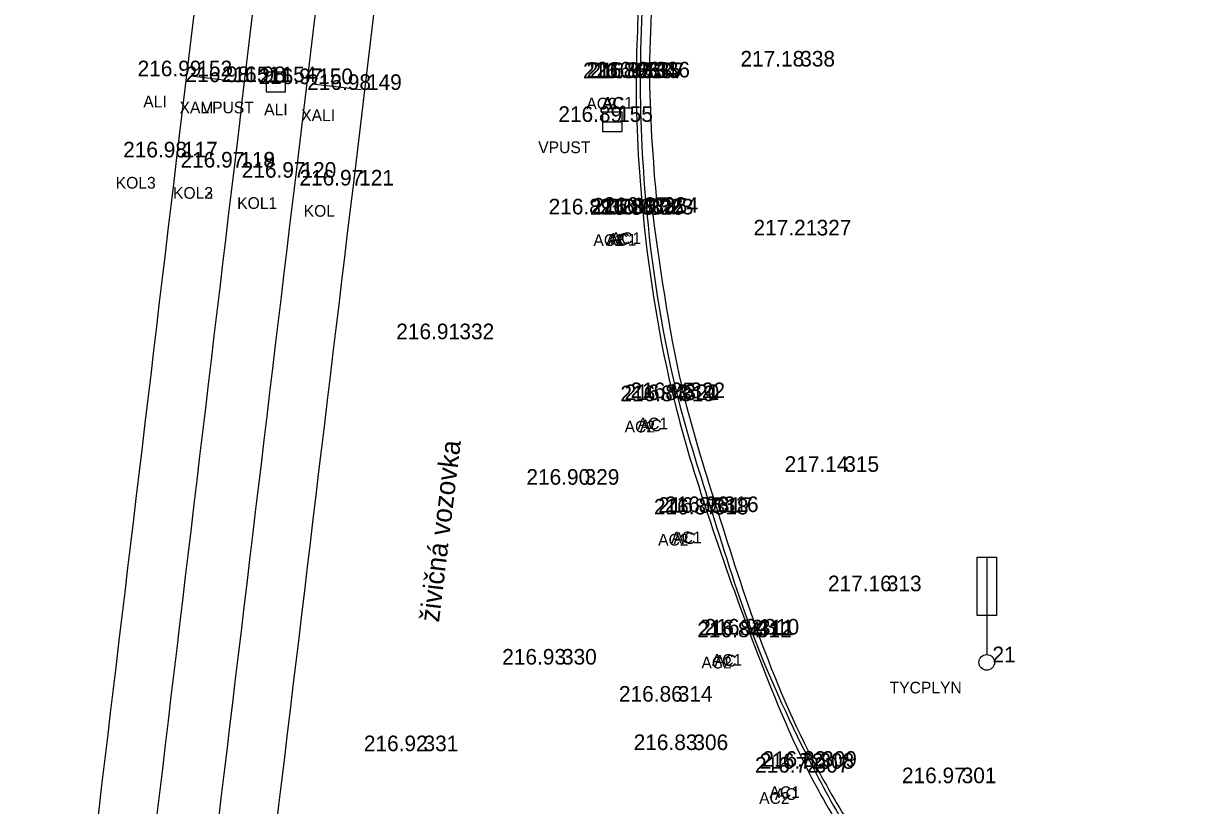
# Model space of a CAD drawing. Extents: x -471047 to -470889, y -1102859 to -1102000.
# Drawn here: x -471001.01 to -470970.75, y -1102729.15 to -1102709.11 of the extents above; entities that cross this region are included whole.
import ezdxf

# ---------------------------------------------------------------- set-up
doc = ezdxf.new("R2010")
doc.units = 0
for name, color, linetype in [('Vrstva 1', 7, 'Continuous'), ('Vrstva 11', 7, 'Continuous'), ('Vrstva 22', 7, 'Continuous'), ('Vrstva 25', 7, 'Continuous'), ('Vrstva 29', 7, 'Continuous'), ('Vrstva 34', 7, 'Continuous'), ('Vrstva 35', 7, 'Continuous'), ('Vrstva 36', 7, 'Continuous'), ('Vrstva 38', 7, 'Continuous'), ('Vrstva 5', 7, 'Continuous'), ('Vrstva 7', 7, 'Continuous'), ('Vrstva 8', 7, 'Continuous')]:
    doc.layers.add(name, color=color, linetype=linetype)

msp = doc.modelspace()

# ---------------------------------------------------------------- linework, layer by layer
at = {"layer": 'Vrstva 1'}
for points in [[(-471040.344, -1102858.385), (-471031.676, -1102846.187), (-471026.357, -1102838.629), (-471023.212, -1102833.975), (-471019.21, -1102827.465), (-471016.861, -1102823.272), (-471013.099, -1102815.912), (-471010.824, -1102810.955), (-471007.329, -1102802.292), (-471005.34, -1102796.515), (-471002.842, -1102787.838), (-471001.3, -1102780.997), (-471000.19, -1102774.713), (-470999.247, -1102768.204), (-470998.794, -1102764.784), (-470997.199, -1102751.812), (-470994.899, -1102732.807), (-470992.551, -1102713.262), (-470990.326, -1102694.887), (-470988.122, -1102676.57), (-470985.812, -1102657.305), (-470983.537, -1102638.407), (-470981.386, -1102620.622), (-470979.843, -1102608.014), (-470976.377, -1102579.253), (-470972.945, -1102550.69), (-470970.475, -1102530.206), (-470967.905, -1102508.801), (-470965.053, -1102485.131), (-470962.734, -1102465.9), (-470960.173, -1102444.812), (-470957.795, -1102425.103), (-470954.965, -1102401.839), (-470953.834, -1102392.574), (-470952.33, -1102379.985), (-470950.744, -1102366.853), (-470948.978, -1102352.106), (-470947.037, -1102335.844), (-470944.949, -1102318.462), (-470944.013, -1102310.745), (-470942.39, -1102297.267), (-470939.519, -1102273.45), (-470937.593, -1102257.43), (-470936.064, -1102244.81), (-470934.114, -1102228.634), (-470931.621, -1102207.856), (-470929.536, -1102190.857), (-470926.572, -1102166.31), (-470924.91, -1102152.663), (-470923.413, -1102140.333), (-470921.923, -1102127.669), (-470921.155, -1102120.084), (-470920.446, -1102109.574), (-470919.912, -1102099.137), (-470919.63, -1102088.981), (-470919.523, -1102081.193), (-470919.563, -1102070.395), (-470919.714, -1102064.236), (-470920.134, -1102054.704), (-470920.462, -1102047.615), (-470920.599, -1102044.52), (-470920.743, -1102041.873), (-470921.125, -1102034.455), (-470921.774, -1102030.337), (-470922.418, -1102027.787), (-470923.734, -1102023.93), (-470924.872, -1102021.434), (-470926.752, -1102018.182), (-470927.953, -1102016.45), (-470929.616, -1102014.424), (-470932.252, -1102011.756), (-470935.111, -1102009.425), (-470938.391, -1102007.371), (-470942.651, -1102005.401)], [(-471041.328, -1102857.18), (-471032.144, -1102844.242), (-471027.583, -1102837.763), (-471024.388, -1102833.028), (-471020.451, -1102826.6), (-471018.089, -1102822.378), (-471014.542, -1102815.445), (-471012.233, -1102810.418), (-471009.247, -1102803.108), (-471006.795, -1102796.098), (-471004.315, -1102787.532), (-471002.782, -1102780.723), (-471001.674, -1102774.458), (-471000.75, -1102768.095), (-471000.28, -1102764.601), (-470998.692, -1102751.741), (-470996.378, -1102732.635), (-470994.028, -1102713.058), (-470991.808, -1102694.749), (-470989.616, -1102676.447), (-470987.284, -1102657.013), (-470985.031, -1102638.272), (-470982.87, -1102620.431), (-470981.334, -1102607.933), (-470977.881, -1102579.263), (-470974.429, -1102550.492), (-470971.964, -1102530.054), (-470969.391, -1102508.607), (-470966.54, -1102484.984), (-470964.231, -1102465.853), (-470961.679, -1102444.752), (-470959.304, -1102425.078), (-470956.455, -1102401.634), (-470955.339, -1102392.489), (-470953.812, -1102379.71), (-470952.249, -1102366.808), (-470950.479, -1102352.023), (-470948.536, -1102335.868), (-470946.426, -1102318.233), (-470945.493, -1102310.531), (-470943.864, -1102297.013), (-470940.984, -1102273.071), (-470939.078, -1102257.195), (-470937.559, -1102244.684), (-470935.592, -1102228.353), (-470933.101, -1102207.653), (-470931.011, -1102190.57), (-470928.046, -1102166.021), (-470926.409, -1102152.578), (-470924.898, -1102140.121), (-470923.427, -1102127.544), (-470922.647, -1102119.826), (-470921.919, -1102109.229), (-470921.42, -1102099.134), (-470921.127, -1102089.016), (-470921.023, -1102081.453), (-470921.061, -1102070.468), (-470921.209, -1102064.314), (-470921.666, -1102053.966), (-470922.156, -1102043.345), (-470922.299, -1102039.934), (-470922.637, -1102034.36), (-470923.091, -1102031.241), (-470923.847, -1102028.247), (-470925.083, -1102024.594), (-470926.222, -1102022.086), (-470928.04, -1102018.943), (-470929.138, -1102017.357), (-470930.929, -1102015.175), (-470933.062, -1102013.049), (-470936.379, -1102010.368), (-470939.169, -1102008.662), (-470942.899, -1102006.906), (-470945.661, -1102005.908)], [(-471043.557, -1102855.955), (-471035.129, -1102844.026), (-471029.872, -1102836.499), (-471026.577, -1102831.578), (-471022.675, -1102825.415), (-471020.123, -1102821.053), (-471016.667, -1102814.59), (-471014.208, -1102809.45), (-471011.177, -1102802.451), (-471008.55, -1102795.333), (-471006.082, -1102787.209), (-471004.464, -1102780.376), (-471003.265, -1102774.167), (-471002.327, -1102767.948), (-471001.636, -1102762.527), (-471000.297, -1102751.605), (-470997.959, -1102732.524), (-470995.602, -1102712.802), (-470993.412, -1102694.623), (-470991.21, -1102676.17), (-470988.891, -1102656.857), (-470986.625, -1102638.083), (-470984.455, -1102620.195), (-470982.936, -1102607.733), (-470979.497, -1102579.223), (-470976.023, -1102550.279), (-470973.554, -1102529.822), (-470970.991, -1102508.497), (-470968.146, -1102484.787), (-470965.835, -1102465.72), (-470963.284, -1102444.529), (-470960.91, -1102424.942), (-470958.043, -1102401.343), (-470956.946, -1102392.356), (-470955.396, -1102379.408), (-470953.851, -1102366.636), (-470952.049, -1102351.733), (-470950.124, -1102335.611), (-470948.034, -1102318.083), (-470947.094, -1102310.328), (-470945.421, -1102296.51), (-470942.58, -1102272.848), (-470940.675, -1102256.948), (-470939.176, -1102244.526), (-470937.187, -1102228.174), (-470934.708, -1102207.467), (-470932.621, -1102190.433), (-470929.634, -1102165.778), (-470928.004, -1102152.415), (-470926.45, -1102139.595), (-470925.003, -1102127.418), (-470924.249, -1102119.695), (-470923.515, -1102109.093), (-470923.018, -1102099.069), (-470922.711, -1102088.911), (-470922.643, -1102081.356), (-470922.797, -1102070.414), (-470923.018, -1102064.454), (-470923.52, -1102053.203), (-470923.823, -1102047.529), (-470924.123, -1102041.506), (-470924.462, -1102037.486), (-470924.934, -1102031.904), (-470925.664, -1102028.672), (-470926.771, -1102025.506), (-470927.959, -1102022.914), (-470929.674, -1102020.028), (-470930.76, -1102018.498), (-470932.447, -1102016.478), (-470935.215, -1102013.816), (-470937.644, -1102011.98), (-470940.381, -1102010.371), (-470943.968, -1102008.669), (-470947.145, -1102007.524), (-470950.874, -1102006.74)], [(-471044.756, -1102855.056), (-471036.376, -1102843.177), (-471031.167, -1102835.741), (-471027.859, -1102830.8), (-471023.934, -1102824.593), (-471021.43, -1102820.312), (-471018.011, -1102813.91), (-471015.536, -1102808.75), (-471012.578, -1102801.897), (-471009.95, -1102794.77), (-471007.561, -1102786.914), (-471005.936, -1102780.074), (-471004.727, -1102773.818), (-471003.828, -1102767.827), (-471003.121, -1102762.345), (-471001.787, -1102751.467), (-470999.446, -1102732.348), (-470997.073, -1102712.539), (-470994.902, -1102694.521), (-470992.696, -1102676.023), (-470990.376, -1102656.68), (-470988.131, -1102638.071), (-470985.947, -1102620.018), (-470984.417, -1102607.512), (-470980.993, -1102579.08), (-470977.514, -1102550.137), (-470975.048, -1102529.649), (-470972.488, -1102508.37), (-470969.618, -1102484.508), (-470967.34, -1102465.669), (-470964.767, -1102444.39), (-470962.402, -1102424.781), (-470959.534, -1102401.193), (-470958.432, -1102392.151), (-470956.883, -1102379.208), (-470955.335, -1102366.424), (-470953.535, -1102351.506), (-470951.606, -1102335.399), (-470949.519, -1102317.94), (-470948.575, -1102310.159), (-470946.889, -1102296.144), (-470944.056, -1102272.618), (-470942.139, -1102256.659), (-470940.657, -1102244.341), (-470938.638, -1102227.749), (-470936.19, -1102207.298), (-470934.102, -1102190.255), (-470931.124, -1102165.639), (-470929.492, -1102152.254), (-470927.915, -1102139.252), (-470926.46, -1102127.103), (-470925.74, -1102119.604), (-470925.012, -1102108.913), (-470924.523, -1102099.054), (-470924.217, -1102088.866), (-470924.148, -1102081.334), (-470924.301, -1102070.391), (-470924.518, -1102064.43), (-470924.97, -1102054.435), (-470925.588, -1102041.569), (-470925.963, -1102035.313), (-470926.405, -1102032.225), (-470927.078, -1102029.198), (-470928.123, -1102026.148), (-470929.318, -1102023.558), (-470930.84, -1102020.97), (-470931.868, -1102019.515), (-470933.443, -1102017.605), (-470936.26, -1102014.885), (-470938.429, -1102013.255), (-470941.213, -1102011.639), (-470944.847, -1102009.927), (-470947.723, -1102008.912), (-470951.444, -1102008.161), (-470954.511, -1102007.931), (-470957.895, -1102008.041)]]:
    msp.add_spline(points, degree=3, dxfattribs=at)
at = {"layer": 'Vrstva 11'}
msp.add_line((-470976.308, -1102722.784), (-470976.308, -1102725.284), dxfattribs=at)
msp.add_lwpolyline([(-470976.558, -1102722.784), (-470976.058, -1102722.784), (-470976.058, -1102724.284), (-470976.558, -1102724.284)], close=True, dxfattribs=at)
msp.add_circle((-470976.308, -1102725.484), 0.2, dxfattribs=at)
at = {"layer": 'Vrstva 25'}
for p, q in [((-470994.79, -1102710.355), (-470994.79, -1102710.855)), ((-470994.29, -1102710.355), (-470994.79, -1102710.355)), ((-470994.29, -1102710.855), (-470994.29, -1102710.355)), ((-470994.79, -1102710.605), (-470994.29, -1102710.605)), ((-470994.79, -1102710.855), (-470994.29, -1102710.855)), ((-470986.16, -1102711.378), (-470986.16, -1102711.878)), ((-470985.66, -1102711.378), (-470986.16, -1102711.378)), ((-470985.66, -1102711.878), (-470985.66, -1102711.378)), ((-470986.16, -1102711.628), (-470985.66, -1102711.628)), ((-470986.16, -1102711.878), (-470985.66, -1102711.878))]:
    msp.add_line(p, q, dxfattribs=at)
at = {"layer": 'Vrstva 29'}
for p, q in [((-470995.466, -1102710.609), (-470996.704, -1102710.456)), ((-470992.352, -1102710.808), (-470993.597, -1102710.658))]:
    msp.add_line(p, q, dxfattribs=at)
at = {"layer": 'Vrstva 34'}
for p, q in [((-470981.24, -1102710.21), (-470981.24, -1102710.21)), ((-470996.7, -1102710.46), (-470996.7, -1102710.46)), ((-470985.3, -1102710.51), (-470985.3, -1102710.51)), ((-470985.19, -1102710.5), (-470985.19, -1102710.5)), ((-470985.11, -1102710.51), (-470985.11, -1102710.51)), ((-470984.96, -1102710.49), (-470984.96, -1102710.49)), ((-470995.47, -1102710.61), (-470995.47, -1102710.61)), ((-470994.54, -1102710.61), (-470994.54, -1102710.61)), ((-470993.6, -1102710.66), (-470993.6, -1102710.66)), ((-470992.35, -1102710.81), (-470992.35, -1102710.81)), ((-470985.91, -1102711.63), (-470985.91, -1102711.63)), ((-470997.07, -1102712.54), (-470997.07, -1102712.54)), ((-470995.6, -1102712.8), (-470995.6, -1102712.8)), ((-470995.6, -1102712.8), (-470995.6, -1102712.8)), ((-470994.03, -1102713.06), (-470994.03, -1102713.06)), ((-470992.55, -1102713.26), (-470992.55, -1102713.26)), ((-470986.16, -1102714), (-470986.16, -1102714)), ((-470985.12, -1102714.01), (-470985.12, -1102714.01)), ((-470985.03, -1102713.98), (-470985.03, -1102713.98)), ((-470984.87, -1102714), (-470984.87, -1102714)), ((-470984.75, -1102713.96), (-470984.75, -1102713.96)), ((-470980.82, -1102714.54), (-470980.82, -1102714.54)), ((-470989.98, -1102717.2), (-470989.98, -1102717.2)), ((-470984.06, -1102718.71), (-470984.06, -1102718.71)), ((-470984.32, -1102718.79), (-470984.32, -1102718.79)), ((-470984.21, -1102718.76), (-470984.21, -1102718.76)), ((-470984.21, -1102718.76), (-470984.21, -1102718.76)), ((-470980.11, -1102720.6), (-470980.11, -1102720.6)), ((-470986.77, -1102720.93), (-470986.77, -1102720.93)), ((-470983.46, -1102721.69), (-470983.46, -1102721.69)), ((-470983.35, -1102721.65), (-470983.35, -1102721.65)), ((-470983.2, -1102721.63), (-470983.2, -1102721.63)), ((-470979.02, -1102723.66), (-470979.02, -1102723.66)), ((-470982.3, -1102724.79), (-470982.3, -1102724.79)), ((-470982.16, -1102724.77), (-470982.16, -1102724.77)), ((-470982.35, -1102724.84), (-470982.35, -1102724.84)), ((-470987.35, -1102725.54), (-470987.35, -1102725.54)), ((-470976.31, -1102725.48), (-470976.31, -1102725.48)), ((-470984.38, -1102726.49), (-470984.38, -1102726.49)), ((-470990.9, -1102727.76), (-470990.9, -1102727.76)), ((-470983.98, -1102727.73), (-470983.98, -1102727.73)), ((-470980.87, -1102728.31), (-470980.87, -1102728.31)), ((-470980.75, -1102728.21), (-470980.75, -1102728.21)), ((-470980.68, -1102728.16), (-470980.68, -1102728.16)), ((-470977.1, -1102728.58), (-470977.1, -1102728.58))]:
    msp.add_line(p, q, dxfattribs=at)
at = {"layer": 'Vrstva 5'}
msp.add_spline([(-470985.188, -1102707.748), (-470985.298, -1102710.513), (-470985.121, -1102714.009), (-470984.319, -1102718.787), (-470983.462, -1102721.691), (-470982.346, -1102724.837), (-470980.868, -1102728.306), (-470979.814, -1102730.112), (-470978.15, -1102732.217), (-470976.904, -1102733.436), (-470974.289, -1102735.317)], degree=3, dxfattribs=at)
at = {"layer": 'Vrstva 7'}
msp.add_line((-470984.874, -1102713.999), (-470984.752, -1102713.964), dxfattribs=at)
for points in [[(-470984.764, -1102706.728), (-470984.956, -1102710.493), (-470984.752, -1102713.964)], [(-470984.874, -1102713.999), (-470984.058, -1102718.71), (-470983.204, -1102721.627), (-470982.162, -1102724.77), (-470980.678, -1102728.163), (-470979.58, -1102730.011), (-470977.967, -1102732.081), (-470976.73, -1102733.233), (-470974.152, -1102735.148)]]:
    msp.add_spline(points, degree=3, dxfattribs=at)
at = {"layer": 'Vrstva 8'}
msp.add_line((-470984.212, -1102718.757), (-470984.214, -1102718.758), dxfattribs=at)
msp.add_spline([(-470985.029, -1102706.638), (-470985.194, -1102710.505), (-470985.025, -1102713.978), (-470984.214, -1102718.758), (-470983.352, -1102721.645), (-470982.297, -1102724.793), (-470980.745, -1102728.214), (-470979.687, -1102730.074), (-470978.076, -1102732.15), (-470976.791, -1102733.373), (-470974.19, -1102735.241)], degree=3, dxfattribs=at)

# ---------------------------------------------------------------- texts
at = {"layer": 'Vrstva 22'}
msp.add_text('živičná vozovka', height=0.5, rotation=83.0936, dxfattribs=at).set_placement((-470990.356, -1102724.468))
at = {"layer": 'Vrstva 35'}
for s, p in [('ALI', (-470997.938, -1102711.26)), ('XALI', (-470997.008, -1102711.41)), ('VPUST', (-470996.44, -1102711.41)), ('ALI', (-470994.838, -1102711.46)), ('AC2', (-470986.575, -1102711.31)), ('AC', (-470986.179, -1102711.3)), ('AC1', (-470986.16, -1102711.29)), ('XALI', (-470993.888, -1102711.61)), ('VPUST', (-470987.81, -1102712.43)), ('KOL3', (-470998.645, -1102713.34)), ('KOL3', (-470997.175, -1102713.6)), ('KOL2', (-470997.175, -1102713.6)), ('KOL1', (-470995.53, -1102713.86)), ('KOL', (-470993.825, -1102714.06)), ('AC2', (-470986.395, -1102714.81)), ('AC1', (-470986.07, -1102714.8)), ('AC', (-470986.019, -1102714.78)), ('AC1', (-470985.95, -1102714.76)), ('AC2', (-470985.595, -1102719.59)), ('AC1', (-470985.26, -1102719.51)), ('AC', (-470985.199, -1102719.56)), ('AC', (-470985.199, -1102719.56)), ('AC2', (-470984.735, -1102722.49)), ('AC1', (-470984.4, -1102722.43)), ('AC', (-470984.339, -1102722.45)), ('AC2', (-470983.625, -1102725.64)), ('AC1', (-470983.36, -1102725.57)), ('AC', (-470983.289, -1102725.59)), ('TYCPLYN', (-470978.799, -1102726.28)), ('AC1', (-470981.88, -1102728.96)), ('AC', (-470981.739, -1102729.01)), ('AC2', (-470982.145, -1102729.11))]:
    msp.add_text(s, height=0.3, dxfattribs=at).set_placement(p)
at = {"layer": 'Vrstva 36'}
for s, p in [(' 338', (-470981.24, -1102710.21)), (' 152', (-470996.7, -1102710.46)), (' 151', (-470995.47, -1102710.61)), (' 154', (-470994.54, -1102710.61)), (' 150', (-470993.6, -1102710.66)), (' 334', (-470985.3, -1102710.51)), (' 335', (-470985.19, -1102710.5)), (' 337', (-470985.11, -1102710.51)), (' 336', (-470984.96, -1102710.49)), (' 149', (-470992.35, -1102710.81)), (' 155', (-470985.91, -1102711.63)), (' 117', (-470997.07, -1102712.54)), (' 118', (-470995.6, -1102712.8)), (' 119', (-470995.6, -1102712.8)), (' 120', (-470994.03, -1102713.06)), (' 121', (-470992.55, -1102713.26)), (' 328', (-470986.16, -1102714)), (' 325', (-470985.03, -1102713.98)), (' 323', (-470984.87, -1102714)), (' 324', (-470984.75, -1102713.96)), (' 326', (-470985.12, -1102714.01)), (' 327', (-470980.82, -1102714.54)), (' 332', (-470989.98, -1102717.2)), (' 319', (-470984.32, -1102718.79)), (' 320', (-470984.21, -1102718.76)), (' 321', (-470984.21, -1102718.76)), (' 322', (-470984.06, -1102718.71)), (' 315', (-470980.11, -1102720.6)), (' 329', (-470986.77, -1102720.93)), (' 318', (-470983.46, -1102721.69)), (' 317', (-470983.35, -1102721.65)), (' 316', (-470983.2, -1102721.63)), (' 313', (-470979.02, -1102723.66)), (' 312', (-470982.35, -1102724.84)), (' 311', (-470982.3, -1102724.79)), (' 310', (-470982.16, -1102724.77)), (' 21', (-470976.31, -1102725.48)), (' 330', (-470987.35, -1102725.54)), (' 314', (-470984.38, -1102726.49)), (' 331', (-470990.9, -1102727.76)), (' 306', (-470983.98, -1102727.73)), (' 308', (-470980.75, -1102728.21)), (' 309', (-470980.68, -1102728.16)), (' 307', (-470980.87, -1102728.31)), (' 301', (-470977.1, -1102728.58))]:
    msp.add_text(s, height=0.4, dxfattribs=at).set_placement(p)
at = {"layer": 'Vrstva 38'}
for s, p in [('217.18 ', (-470982.624, -1102710.21)), ('216.99 ', (-470998.084, -1102710.46)), ('216.98 ', (-470996.854, -1102710.61)), ('216.98 ', (-470995.924, -1102710.61)), ('216.97 ', (-470994.983, -1102710.66)), ('216.86 ', (-470986.66, -1102710.51)), ('216.82 ', (-470986.571, -1102710.5)), ('216.95 ', (-470986.494, -1102710.51)), ('216.96 ', (-470986.32, -1102710.49)), ('216.98 ', (-470993.734, -1102710.81)), ('216.89 ', (-470987.294, -1102711.63)), ('216.98 ', (-470998.454, -1102712.54)), ('216.97 ', (-470996.983, -1102712.8)), ('216.97 ', (-470996.983, -1102712.8)), ('216.97 ', (-470995.413, -1102713.06)), ('216.97 ', (-470993.933, -1102713.26)), ('216.89 ', (-470987.544, -1102714)), ('216.85 ', (-470986.414, -1102713.98)), ('216.96 ', (-470986.23, -1102714)), ('216.97 ', (-470986.133, -1102713.96)), ('216.86 ', (-470986.48, -1102714.01)), ('217.21 ', (-470982.29, -1102714.54)), ('216.91 ', (-470991.45, -1102717.2)), ('216.84 ', (-470985.702, -1102718.79)), ('216.83 ', (-470985.593, -1102718.76)), ('216.83 ', (-470985.593, -1102718.76)), ('216.95 ', (-470985.444, -1102718.71)), ('217.14 ', (-470981.492, -1102720.6)), ('216.90 ', (-470988.113, -1102720.93)), ('216.87 ', (-470984.843, -1102721.69)), ('216.85 ', (-470984.734, -1102721.65)), ('216.96 ', (-470984.56, -1102721.63)), ('217.16 ', (-470980.38, -1102723.66)), ('216.84 ', (-470983.732, -1102724.84)), ('216.82 ', (-470983.681, -1102724.79)), ('216.94 ', (-470983.542, -1102724.77)), ('216.93 ', (-470988.733, -1102725.54)), ('216.86 ', (-470985.74, -1102726.49)), ('216.92 ', (-470992.281, -1102727.76)), ('216.83 ', (-470985.363, -1102727.73)), ('216.72 ', (-470982.131, -1102728.21)), ('216.83 ', (-470982.063, -1102728.16)), ('216.72 ', (-470982.251, -1102728.31)), ('216.97 ', (-470978.483, -1102728.58))]:
    msp.add_text(s, height=0.4, dxfattribs=at).set_placement(p)

doc.saveas('drawing.dxf')
